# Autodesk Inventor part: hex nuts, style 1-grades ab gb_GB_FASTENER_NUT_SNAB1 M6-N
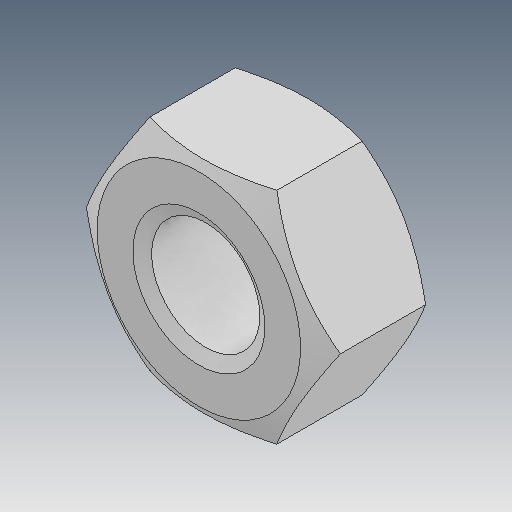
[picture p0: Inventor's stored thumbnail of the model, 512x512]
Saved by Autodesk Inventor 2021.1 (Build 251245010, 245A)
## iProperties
Created: 2019-04
Part Number: hex nuts, style 1-grades ab gb_GB_FASTENER_NUT_SNAB1 M6-N
Material: Ogólny
Document SubType Name: Modeling
Designer: user
Density: 1 g/cm^3
Appearance: Domyślna
Author: user
Revision Number: ÈÎºÎ
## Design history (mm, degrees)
feature "ÊäÈë1"
node "Bryła1"
